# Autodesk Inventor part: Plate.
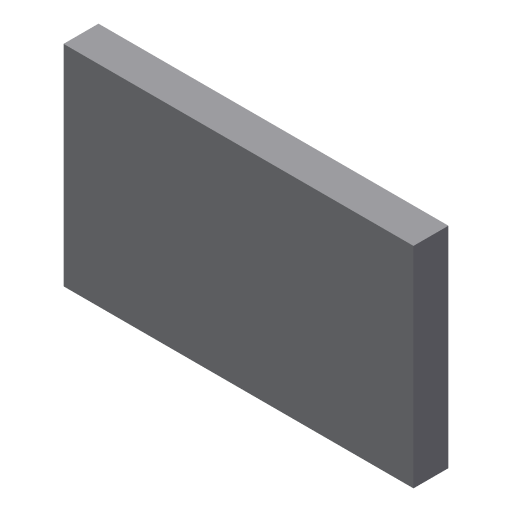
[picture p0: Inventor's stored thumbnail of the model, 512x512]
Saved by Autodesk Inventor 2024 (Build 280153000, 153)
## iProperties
Created: 2010-05
Part Number: Plate.
Document SubType Name: Modeling
Designer: CADSoft
Density: 1 g/cm^3
Material: Generic
Appearance: Default
Author: CADSoft
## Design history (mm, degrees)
sketch "Sketch1"
  geometry: L1 (101.431, -46.382)-(51.431, -46.382); L2 (51.431, -46.382)-(51.431, -76.382); L3 (51.431, -76.382)-(101.431, -76.382); L4 (101.431, -76.382)-(101.431, -46.382); 1 further point
  constraints: 8 end point, 2 parallel, 1 horizontal, 1 perpendicular
  dimensions: "d0" = 30 distance of L3.end L1.start; "d1" = 50 distance of L1.start L1.end
extrude "Extrusion1" new body sketch "Sketch1" distance "d2" = 5; taper "d3" = 0 deg
body "Solid1"
